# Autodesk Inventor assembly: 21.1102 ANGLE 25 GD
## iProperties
Created: 2007-01
Part Number: 21.1102 ANGLE 25 GD
Document SubType Name: Assembly
Designer: Andy Moles
Mass: 73.8298 g
Surface Area: 103.762 cm^2
Volume: 19.3836 cm^3
Density: 3.80889 g/cm^3
Author: Andy Moles
